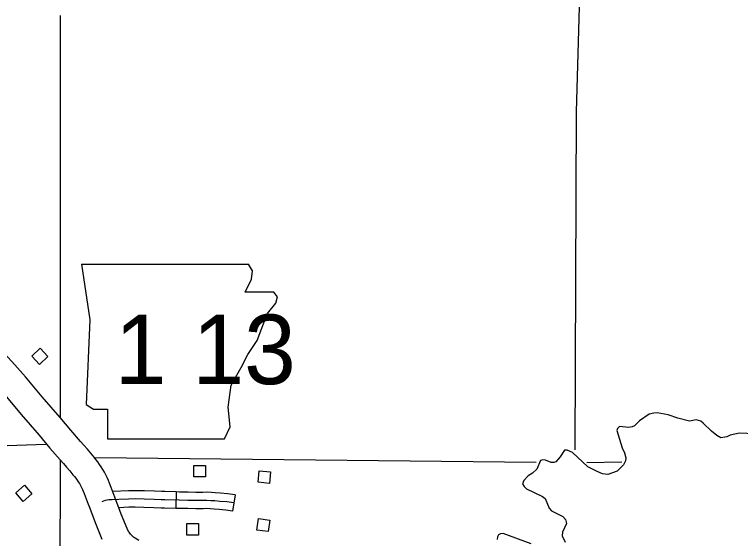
# Model space of a CAD drawing. Extents: x -19 to 366, y -4 to 359.
# Drawn here: x 133.386 to 134.638, y 200.95 to 201.853 of the extents above; entities that cross this region are included whole.
import ezdxf

# ---------------------------------------------------------------- set-up
doc = ezdxf.new("R2010")
doc.units = 0
for name, color, linetype in [('21', 7, 'Continuous'), ('R_Axis', 7, 'Continuous'), ('R_Axis Annot', 7, 'Continuous'), ('R_Border Prem', 7, 'Continuous'), ('R_Contour Annot', 7, 'Continuous'), ('R_Fin Surface Annot', 7, 'Continuous'), ('R_ROW Annot', 7, 'Continuous'), ('Sheet Fence', 7, 'Continuous')]:
    doc.layers.add(name, color=color, linetype=linetype)

msp = doc.modelspace()

# ---------------------------------------------------------------- linework, layer by layer
at = {"layer": '21'}
for points in [[(133.4438, 201.2636), (133.4295, 201.25), (133.4159, 201.2644), (133.4303, 201.2779)], [(133.6955, 201.0559), (133.6955, 201.0756), (133.7152, 201.0756), (133.7152, 201.0559)], [(133.8061, 201.0468), (133.808, 201.0664), (133.8277, 201.0645), (133.8258, 201.0449)], [(133.4032, 201.0417), (133.4162, 201.0269), (133.4013, 201.0138), (133.3883, 201.0287)], [(133.8233, 200.9617), (133.8038, 200.9645), (133.8066, 200.9841), (133.8261, 200.9813)], [(133.6833, 200.9559), (133.6833, 200.9756), (133.7031, 200.9756), (133.7031, 200.9559)]]:
    msp.add_lwpolyline(points, close=True, dxfattribs=at)
at = {"layer": 'R_Axis'}
for points in [[(133.4656, 201.1592), (133.4657, 201.8513)], [(133.4636, 200.4803), (133.4655, 201.0842)]]:
    msp.add_lwpolyline(points, dxfattribs=at)
at = {"layer": 'R_Axis Annot'}
for points in [[(134.3528, 201.1029), (134.3551, 201.6851), (134.3662, 202.0884)], [(133.4403, 201.112), (132.4715, 201.0786)], [(133.5248, 201.0893), (134.2853, 201.0812)], [(134.3728, 201.081), (134.4331, 201.0823)]]:
    msp.add_lwpolyline(points, dxfattribs=at)
at = {"layer": 'R_Border Prem'}
for points in [[(134.6609, 201.1304), (134.6359, 201.1312), (134.6197, 201.1279), (134.6141, 201.1252), (134.6035, 201.1235), (134.5966, 201.1272), (134.5874, 201.1347), (134.5732, 201.1489), (134.569, 201.1519), (134.5614, 201.1544), (134.5497, 201.152), (134.5295, 201.157), (134.5128, 201.1628), (134.4942, 201.1664), (134.4881, 201.1659), (134.4802, 201.1639), (134.4634, 201.1526), (134.4548, 201.1442), (134.4507, 201.1422), (134.4454, 201.1414), (134.4291, 201.1427), (134.4253, 201.1392), (134.4243, 201.1362), (134.4334, 201.1059), (134.4377, 201.0977), (134.4397, 201.089), (134.4391, 201.0836), (134.4357, 201.0771), (134.4249, 201.066), (134.4088, 201.0601), (134.3997, 201.0611), (134.3905, 201.0651)], [(134.3905, 201.0651), (134.3745, 201.0736), (134.348, 201.0979), (134.3388, 201.102), (134.3343, 201.1019), (134.3265, 201.0908), (134.3191, 201.0823), (134.3157, 201.0808), (134.3115, 201.0807), (134.3013, 201.0847), (134.2971, 201.0854), (134.2926, 201.0842), (134.2867, 201.0694), (134.2793, 201.0624), (134.2718, 201.0581), (134.2639, 201.0497), (134.2617, 201.0443), (134.2645, 201.0395), (134.2687, 201.0357), (134.2965, 201.0221), (134.3011, 201.0187), (134.3078, 201.0021), (134.312, 200.9976), (134.3315, 200.9877), (134.3361, 200.9824), (134.3374, 200.976), (134.3308, 200.9607), (134.3301, 200.9543), (134.3352, 200.9433)], [(134.2766, 200.9406), (134.2286, 200.9585), (134.2241, 200.9581), (134.2203, 200.9561), (134.2185, 200.9527), (134.2182, 200.9481)]]:
    msp.add_lwpolyline(points, dxfattribs=at)
at = {"layer": 'R_Contour Annot'}
msp.add_line((133.5147, 201.0049), (133.5148, 201.0049), dxfattribs=at)
for points in [[(133.5591, 201.0214), (133.5575, 201.0258), (133.5501, 201.0452), (133.5482, 201.05), (133.546, 201.0548), (133.5436, 201.0595), (133.5412, 201.0642), (133.5385, 201.0687), (133.5358, 201.0732), (133.5329, 201.0776), (133.5298, 201.0819), (133.5266, 201.086), (133.5235, 201.0898), (133.5178, 201.0967), (133.512, 201.1037), (133.5059, 201.1106), (133.5, 201.1172), (133.4831, 201.1365), (133.4646, 201.1583), (133.434, 201.1941), (133.4051, 201.2284), (133.3865, 201.2494), (133.3581, 201.2803)], [(133.3693, 201.1975), (133.3979, 201.1635), (133.4285, 201.1277), (133.4472, 201.1055), (133.4647, 201.0857), (133.4705, 201.0792), (133.476, 201.0729), (133.4814, 201.0665), (133.4868, 201.0598), (133.4894, 201.0566), (133.4917, 201.0537), (133.4939, 201.0507), (133.4959, 201.0476), (133.4979, 201.0444), (133.4998, 201.0412), (133.5015, 201.0379), (133.5032, 201.0346), (133.5047, 201.0312), (133.5061, 201.0277), (133.5132, 201.0091), (133.5147, 201.0049)], [(133.6003, 200.9464), (133.5939, 200.9503), (133.5927, 200.9511), (133.5912, 200.9523), (133.5899, 200.9535), (133.5885, 200.9548), (133.5873, 200.9562), (133.5861, 200.9576), (133.5849, 200.9591), (133.5838, 200.9607), (133.5828, 200.9622), (133.5819, 200.9638), (133.5811, 200.9655), (133.5802, 200.9674), (133.5701, 200.992), (133.5591, 201.0214)], [(133.5148, 201.0049), (133.5261, 200.9747), (133.5367, 200.9488)]]:
    msp.add_lwpolyline(points, dxfattribs=at)
at = {"layer": 'R_Fin Surface Annot'}
for p, q in [((133.5016, 201.4227), (133.516, 201.3266)), ((133.7963, 201.4115), (133.7897, 201.4226)), ((133.7947, 201.3971), (133.7963, 201.4115)), ((133.7835, 201.3746), (133.7947, 201.3971)), ((133.8332, 201.3746), (133.7835, 201.3746)), ((133.8396, 201.3666), (133.8332, 201.3746)), ((133.8364, 201.3554), (133.8396, 201.3666)), ((133.822, 201.3378), (133.8364, 201.3554)), ((133.814, 201.317), (133.822, 201.3378)), ((133.516, 201.3266), (133.5096, 201.1808)), ((133.8043, 201.2913), (133.814, 201.317)), ((133.7883, 201.2673), (133.8043, 201.2913)), ((133.7771, 201.2449), (133.7883, 201.2673)), ((133.7595, 201.2144), (133.7771, 201.2449)), ((133.7547, 201.176), (133.7595, 201.2144)), ((133.5096, 201.1808), (133.5224, 201.1728)), ((133.5224, 201.1728), (133.5464, 201.1728)), ((133.5464, 201.1728), (133.5464, 201.1215)), ((133.7579, 201.1423), (133.7547, 201.176)), ((133.7483, 201.1215), (133.7579, 201.1423)), ((133.5464, 201.1215), (133.7483, 201.1215))]:
    msp.add_line(p, q, dxfattribs=at)
msp.add_lwpolyline([(133.5016, 201.4227), (133.7897, 201.4226)], dxfattribs=at)
at = {"layer": 'R_ROW Annot'}
for p, q in [((133.6649, 201.0301), (133.664, 201.0017)), ((133.7663, 201.0252), (133.7621, 200.9971))]:
    msp.add_line(p, q, dxfattribs=at)
for points in [[(133.6649, 201.0301), (133.6455, 201.0307), (133.6394, 201.0308), (133.6276, 201.0312), (133.6101, 201.0318), (133.5944, 201.0323), (133.5824, 201.032), (133.5555, 201.0311)], [(133.7663, 201.0252), (133.7535, 201.0271), (133.7414, 201.028), (133.7323, 201.0288), (133.7256, 201.0292), (133.718, 201.0298), (133.7108, 201.0294), (133.6989, 201.0293), (133.6855, 201.0297), (133.6704, 201.0299), (133.6649, 201.0301)], [(133.7642, 201.0112), (133.7519, 201.013), (133.7403, 201.0138), (133.7312, 201.0146), (133.7246, 201.015), (133.7178, 201.0155), (133.7112, 201.0152), (133.6987, 201.0151), (133.6852, 201.0155), (133.6701, 201.0157), (133.6451, 201.0165), (133.639, 201.0166), (133.6271, 201.017), (133.6096, 201.0176), (133.5944, 201.0181), (133.5828, 201.0178), (133.5662, 201.0173), (133.5544, 201.0168), (133.5489, 201.0167), (133.5458, 201.0162), (133.5423, 201.0155), (133.5369, 201.0132)], [(133.664, 201.0017), (133.6448, 201.0023), (133.6387, 201.0024), (133.6266, 201.0028), (133.6091, 201.0034), (133.5944, 201.0039), (133.5832, 201.0036), (133.566, 201.003)], [(133.7621, 200.9971), (133.7504, 200.9989), (133.7392, 200.9997), (133.7301, 201.0004), (133.7236, 201.0009), (133.7176, 201.0013), (133.7116, 201.001), (133.6986, 201.0009), (133.6849, 201.0013), (133.6697, 201.0015), (133.664, 201.0017)]]:
    msp.add_lwpolyline(points, dxfattribs=at)
at = {"layer": 'Sheet Fence'}
for points in [[(139.4406, 1.5315), (139.2511, 10.1473), (139.0608, 18.7633), (138.8699, 27.3793), (138.6784, 35.9956), (138.4861, 44.6119), (138.2932, 53.2285), (138.0997, 61.8451), (137.9055, 70.4619), (137.7106, 79.0789), (137.5151, 87.6959), (137.319, 96.3132), (137.1221, 104.9306), (136.9247, 113.5481), (136.7265, 122.1658), (136.5278, 130.7836), (136.3283, 139.4016), (136.1282, 148.0197), (135.9275, 156.6379), (135.7261, 165.2564), (135.5241, 173.8749), (135.3214, 182.4936), (135.1181, 191.1125), (134.9141, 199.7315), (134.7095, 208.3506), (134.5043, 216.9699), (134.2984, 225.5894), (134.0919, 234.209), (133.8847, 242.8288), (133.6769, 251.4487), (133.4685, 260.0687), (133.2594, 268.6889), (133.0497, 277.3093), (132.8393, 285.9298), (132.6283, 294.5504), (132.4167, 303.1713), (132.2044, 311.7922), (131.9916, 320.4133), (131.778, 329.0346), (131.5639, 337.656), (131.3491, 346.2776)], [(0, 198.1326), (7.1014, 198.137), (14.2028, 198.1503), (21.3042, 198.1724), (28.4055, 198.2034), (35.5068, 198.2433), (42.6081, 198.292), (49.7092, 198.3496), (56.8103, 198.4161), (63.9113, 198.4913), (71.0123, 198.5755), (78.1131, 198.6685), (85.2137, 198.7704), (92.3143, 198.8811), (99.4147, 199.0007), (106.5149, 199.1291), (113.615, 199.2664), (120.7149, 199.4126), (127.8146, 199.5676), (134.9141, 199.7315), (142.0135, 199.9042), (149.1125, 200.0858), (156.2114, 200.2762), (163.31, 200.4755), (170.4084, 200.6837), (177.5065, 200.9007), (184.6043, 201.1265), (191.7018, 201.3612), (198.799, 201.6048), (205.896, 201.8572), (212.9926, 202.1185), (220.0888, 202.3886), (227.1848, 202.6676), (234.2803, 202.9554), (241.3755, 203.2521), (248.4704, 203.5576), (255.5648, 203.872), (262.6589, 204.1952), (269.7525, 204.5273), (276.8457, 204.8682), (283.9385, 205.218), (291.0309, 205.5766), (298.1228, 205.9441), (305.2142, 206.3204), (312.3051, 206.7056), (319.3956, 207.0996), (326.4856, 207.5024), (333.5751, 207.9141), (340.664, 208.3347)]]:
    msp.add_spline(points, degree=3, dxfattribs=at)

# ---------------------------------------------------------------- texts
at = {"layer": 'R_Fin Surface Annot'}
msp.add_text('1 13', height=0.12, dxfattribs=at).set_placement((133.5588, 201.2159))

doc.saveas('drawing.dxf')
